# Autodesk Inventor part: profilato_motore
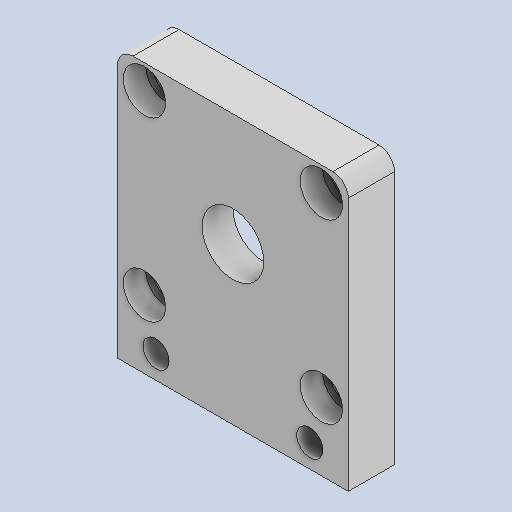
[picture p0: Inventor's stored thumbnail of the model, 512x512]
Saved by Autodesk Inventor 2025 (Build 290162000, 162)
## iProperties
Created: 2025-11
Part Number: profilato_motore
Material: Generico
Document SubType Name: Modeling
Designer: Ryzen5700u
Density: 1 g/cm^3
Appearance: Default
Author: Ryzen5700u
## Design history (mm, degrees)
feature "Solido3"
node "Solido1"
